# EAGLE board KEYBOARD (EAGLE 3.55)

No outline drawn. Coordinates in mm, seen from the top.
Copper layers used: 

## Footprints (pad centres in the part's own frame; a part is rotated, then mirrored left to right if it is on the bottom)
NDBTN = drill 1.27 pad 1.676 octagon:  3.175,-0.635;  -0.635,-1.905;  -3.175,0.635
04/5 = drill 0.813 pad 1.6 octagon:  -2.54,0;  2.54,0
900 = drill 0.813 pad 1.6 octagon:  -3.81,0;  3.81,0

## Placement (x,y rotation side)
E$1  [NDBTN]  15.24,53.34 0 top
E$2  [NDBTN]  15.24,41.91 0 top
E$3  [NDBTN]  15.24,29.21 0 top
E$4  [NDBTN]  15.24,16.51 0 top
E$5  [NDBTN]  29.21,53.34 0 top
E$6  [NDBTN]  29.21,41.91 0 top
E$7  [NDBTN]  29.21,29.21 0 top
E$8  [NDBTN]  29.21,16.51 0 top
E$9  [NDBTN]  43.18,53.34 0 top
E$10  [NDBTN]  43.18,41.91 0 top
E$11  [NDBTN]  43.18,29.21 0 top
E$12  [NDBTN]  43.18,16.51 0 top
E$13  [04/5]  43.18,63.5 270 top
E$14  [04/5]  29.21,63.5 270 top
E$15  [04/5]  15.24,63.5 270 top
E$16  [04/5]  59.69,53.34 0 top
E$17  [04/5]  59.69,41.91 0 top
E$18  [04/5]  59.69,29.21 0 top
E$19  [04/5]  59.69,16.51 0 top
E$20  [900]  38.1,1.27 0 bottom
E$21  [900]  24.13,5.08 0 bottom
E$22  [900]  10.16,7.62 0 bottom

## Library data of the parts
E$1-E$12 = buttons
E$13-E$19 = r
E$20-E$22 = diode

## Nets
S$1: E$1. E$5. E$9. E$16.
S$2: E$2. E$6. E$10. E$17.
S$3: E$3. E$7. E$11. E$18.
S$4: E$4. E$8. E$12. E$19.
S$5: E$1. E$2. E$3. E$4. E$15. E$22.
S$6: E$5. E$6. E$7. E$8. E$14. E$21.
S$7: E$9. E$10. E$11. E$12. E$13. E$20.
S$8: E$16. E$17. E$18. E$19.
S$9: E$13. E$14. E$15.

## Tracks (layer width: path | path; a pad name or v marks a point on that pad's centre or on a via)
S$1  (3 unrouted)
S$2  (3 unrouted)
S$3  (3 unrouted)
S$4  (3 unrouted)
S$5  (5 unrouted)
S$6  (5 unrouted)
S$7  (5 unrouted)
S$8  (3 unrouted)
S$9  (2 unrouted)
